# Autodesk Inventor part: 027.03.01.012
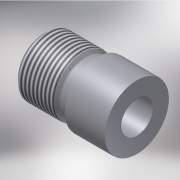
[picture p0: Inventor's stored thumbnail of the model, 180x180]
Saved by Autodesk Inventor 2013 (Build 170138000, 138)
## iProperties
Created: 2005-03
Part Number: 027.03.01.012
Material: Steel, Mild
Document SubType Name: Modeling
Designer: HKostja
Manufacturer: Standard
Standards Organization: Custom
Density: 7.86 g/cm^3
Mass: 77.2847 g
Surface Area: 44.3181 cm^2
Volume: 9.83265 cm^3
Author: HKostja
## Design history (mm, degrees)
revolve "Вращение1" stored, may be unused: angle "d16" = 90 deg
feature "Резьба1" dims "d17" = 10, "d18" = 0
body "Solid1"
sketch "Эскиз1"
  geometry: L1 (0, 0)-(-35, 0); L2 (-35, 9)-(-35, 9.4); L3 (-33.4, 11)-(-20.1, 11); L4 (-20.1, 11)-(-19.146, 10.046); L5 (-18.793, 9.9)-(-16, 9.9); L6 (-15, 10.9)-(-15, 12); L7 (-15, 12)-(0, 12); L8 (0, 12)-(0, 6); L9 (0, 6)-(-32, 6); L10 (-32, 6)-(-35, 9); L11 (-35, 9.4)-(-33.4, 11); A1 r 0.5 centre (-18.793, 10.4) between (-19.146, 10.046) and (-18.793, 9.9); A2 r 1 centre (-16, 10.9) between (-16, 9.9) and (-15, 10.9); 2 further points
  constraints: 22 end point, 6 parallel, 4 point on circle, 4 point on line, 4 tangent, 2 centre point, 1 horizontal, 1 perpendicular, 1 other
  dimensions: "d0" = 35 distance of L1.start L1.end; "d1" = 0 distance from line of L1.end L2; "d2" = 0 distance from line of L1.start L8; "d3" = 20 distance between parallel lines of L6 L2; "d4" = 4 distance from line of point (-19, 9.9) L6; "d5" = 45 deg angle of L5 L4; "d6" = 45 deg angle of L9 L10; "d7" = 24 diameter of L7 L1; "d8" = 22 diameter of L3 L1; "d9" = 19.8 diameter of L5 L1; "d10" = 12 diameter of L9 L1; "d11" = 18 diameter of L2.start L1; "d12" = 0.5 radius of A1; "d13" = 1 radius of A2; "d14" = 1.6 distance of L2.end point (-35, 11); "d15" = 1.6 distance of L3.start point (-35, 11) (= d14)
